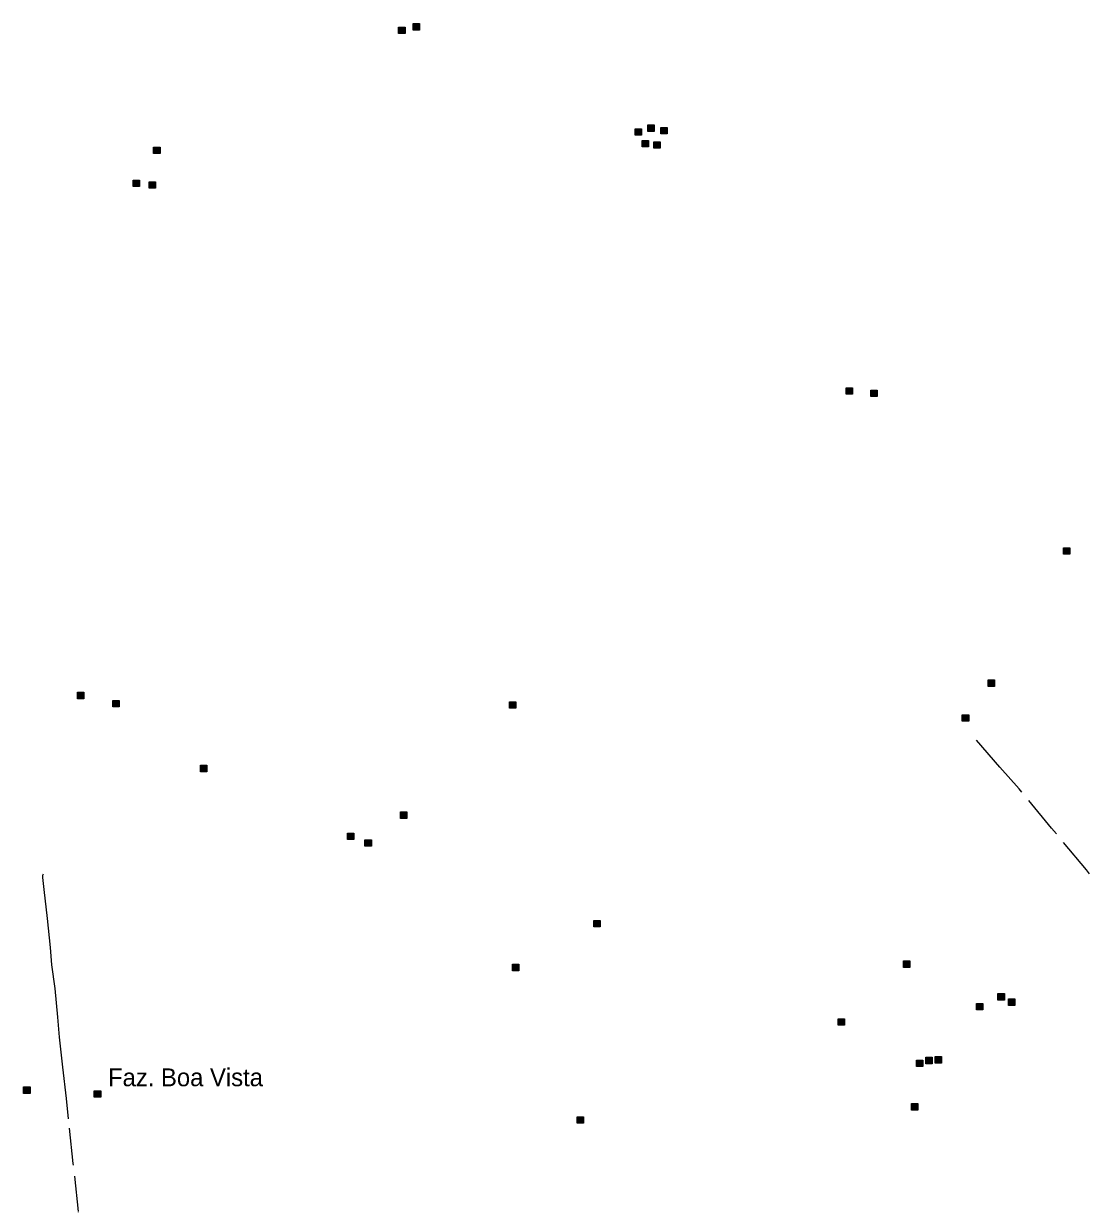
# Model space of a CAD drawing. Extents: x 393.5 to 446.9, y 8064.8 to 8120.4.
# Drawn here: x 437.25 to 446.82, y 8098.67 to 8109.28 of the extents above; entities that cross this region are included whole.
import ezdxf

# ---------------------------------------------------------------- set-up
doc = ezdxf.new("R2010")
doc.units = 0
doc.header["$LTSCALE"] = 0.064
doc.linetypes.add('DOT_DASHED', pattern=[7.7, 5, -1.2, 0.3, -1.2])
doc.layers.add('2', color=7, linetype='Continuous', lineweight=25)
doc.layers.add('22', color=7, linetype='DOT_DASHED', lineweight=13)
doc.layers.add('61', color=7, linetype='Continuous')

msp = doc.modelspace()

# ---------------------------------------------------------------- hatches: boundary and pattern name
at = {"layer": '2'}
for points in [[(440.6124, 8109.246), (440.6704, 8109.246), (440.6704, 8109.188), (440.6124, 8109.188)], [(440.7438, 8109.2772), (440.8018, 8109.2772), (440.8018, 8109.2192), (440.7438, 8109.2192)], [(442.7368, 8108.3317), (442.7948, 8108.3317), (442.7948, 8108.2737), (442.7368, 8108.2737)], [(442.8504, 8108.3665), (442.9084, 8108.3665), (442.9084, 8108.3085), (442.8504, 8108.3085)], [(442.9672, 8108.3451), (443.0252, 8108.3451), (443.0252, 8108.2871), (442.9672, 8108.2871)], [(438.4126, 8108.1683), (438.4706, 8108.1683), (438.4706, 8108.1103), (438.4126, 8108.1103)], [(442.7988, 8108.2276), (442.8568, 8108.2276), (442.8568, 8108.1696), (442.7988, 8108.1696)], [(442.9037, 8108.2149), (442.9617, 8108.2149), (442.9617, 8108.1569), (442.9037, 8108.1569)], [(438.2294, 8107.8717), (438.2874, 8107.8717), (438.2874, 8107.8137), (438.2294, 8107.8137)], [(438.3729, 8107.8561), (438.4309, 8107.8561), (438.4309, 8107.7981), (438.3729, 8107.7981)], [(444.6322, 8106.0064), (444.6902, 8106.0064), (444.6902, 8105.9484), (444.6322, 8105.9484)], [(444.853, 8105.9847), (444.911, 8105.9847), (444.911, 8105.9267), (444.853, 8105.9267)], [(446.5829, 8104.5696), (446.6409, 8104.5696), (446.6409, 8104.5116), (446.5829, 8104.5116)], [(445.9063, 8103.3817), (445.9643, 8103.3817), (445.9643, 8103.3237), (445.9063, 8103.3237)], [(437.7293, 8103.2704), (437.7873, 8103.2704), (437.7873, 8103.2124), (437.7293, 8103.2124)], [(438.0468, 8103.1968), (438.1048, 8103.1968), (438.1048, 8103.1388), (438.0468, 8103.1388)], [(441.6083, 8103.1857), (441.6663, 8103.1857), (441.6663, 8103.1277), (441.6083, 8103.1277)], [(445.6751, 8103.068), (445.7331, 8103.068), (445.7331, 8103.01), (445.6751, 8103.01)], [(438.8329, 8102.6152), (438.8909, 8102.6152), (438.8909, 8102.5572), (438.8329, 8102.5572)], [(440.6298, 8102.1951), (440.6878, 8102.1951), (440.6878, 8102.1371), (440.6298, 8102.1371)], [(440.1537, 8102.0062), (440.2117, 8102.0062), (440.2117, 8101.9482), (440.1537, 8101.9482)], [(440.3106, 8101.9461), (440.3686, 8101.9461), (440.3686, 8101.8881), (440.3106, 8101.8881)], [(442.3662, 8101.2209), (442.4242, 8101.2209), (442.4242, 8101.1629), (442.3662, 8101.1629)], [(445.1455, 8100.8572), (445.2035, 8100.8572), (445.2035, 8100.7992), (445.1455, 8100.7992)], [(441.6344, 8100.8274), (441.6924, 8100.8274), (441.6924, 8100.7694), (441.6344, 8100.7694)], [(445.9949, 8100.5642), (446.0529, 8100.5642), (446.0529, 8100.5062), (445.9949, 8100.5062)], [(445.8022, 8100.4751), (445.8602, 8100.4751), (445.8602, 8100.4171), (445.8022, 8100.4171)], [(446.0899, 8100.5153), (446.1479, 8100.5153), (446.1479, 8100.4573), (446.0899, 8100.4573)], [(444.5598, 8100.3371), (444.6178, 8100.3371), (444.6178, 8100.2791), (444.5598, 8100.2791)], [(445.4303, 8099.9975), (445.4883, 8099.9975), (445.4883, 8099.9395), (445.4303, 8099.9395)], [(445.2639, 8099.9658), (445.3219, 8099.9658), (445.3219, 8099.9078), (445.2639, 8099.9078)], [(445.3464, 8099.9923), (445.4044, 8099.9923), (445.4044, 8099.9343), (445.3464, 8099.9343)], [(437.2454, 8099.7252), (437.3034, 8099.7252), (437.3034, 8099.6672), (437.2454, 8099.6672)], [(437.8797, 8099.69), (437.9377, 8099.69), (437.9377, 8099.632), (437.8797, 8099.632)], [(445.2187, 8099.5756), (445.2767, 8099.5756), (445.2767, 8099.5176), (445.2187, 8099.5176)], [(442.2164, 8099.4574), (442.2744, 8099.4574), (442.2744, 8099.3994), (442.2164, 8099.3994)]]:
    msp.add_hatch(color=256, dxfattribs=at).paths.add_polyline_path(points)

# ---------------------------------------------------------------- linework, layer by layer
for points in [[(440.6124, 8109.246), (440.6704, 8109.246), (440.6704, 8109.188), (440.6124, 8109.188)], [(440.7438, 8109.2772), (440.8018, 8109.2772), (440.8018, 8109.2192), (440.7438, 8109.2192)], [(442.7368, 8108.3317), (442.7948, 8108.3317), (442.7948, 8108.2737), (442.7368, 8108.2737)], [(442.8504, 8108.3665), (442.9084, 8108.3665), (442.9084, 8108.3085), (442.8504, 8108.3085)], [(442.9672, 8108.3451), (443.0252, 8108.3451), (443.0252, 8108.2871), (442.9672, 8108.2871)], [(438.4126, 8108.1683), (438.4706, 8108.1683), (438.4706, 8108.1103), (438.4126, 8108.1103)], [(442.7988, 8108.2276), (442.8568, 8108.2276), (442.8568, 8108.1696), (442.7988, 8108.1696)], [(442.9037, 8108.2149), (442.9617, 8108.2149), (442.9617, 8108.1569), (442.9037, 8108.1569)], [(438.2294, 8107.8717), (438.2874, 8107.8717), (438.2874, 8107.8137), (438.2294, 8107.8137)], [(438.3729, 8107.8561), (438.4309, 8107.8561), (438.4309, 8107.7981), (438.3729, 8107.7981)], [(444.6322, 8106.0064), (444.6902, 8106.0064), (444.6902, 8105.9484), (444.6322, 8105.9484)], [(444.853, 8105.9847), (444.911, 8105.9847), (444.911, 8105.9267), (444.853, 8105.9267)], [(446.5829, 8104.5696), (446.6409, 8104.5696), (446.6409, 8104.5116), (446.5829, 8104.5116)], [(445.9063, 8103.3817), (445.9643, 8103.3817), (445.9643, 8103.3237), (445.9063, 8103.3237)], [(437.7293, 8103.2704), (437.7873, 8103.2704), (437.7873, 8103.2124), (437.7293, 8103.2124)], [(438.0468, 8103.1968), (438.1048, 8103.1968), (438.1048, 8103.1388), (438.0468, 8103.1388)], [(441.6083, 8103.1857), (441.6663, 8103.1857), (441.6663, 8103.1277), (441.6083, 8103.1277)], [(445.6751, 8103.068), (445.7331, 8103.068), (445.7331, 8103.01), (445.6751, 8103.01)], [(438.8329, 8102.6152), (438.8909, 8102.6152), (438.8909, 8102.5572), (438.8329, 8102.5572)], [(440.6298, 8102.1951), (440.6878, 8102.1951), (440.6878, 8102.1371), (440.6298, 8102.1371)], [(440.1537, 8102.0062), (440.2117, 8102.0062), (440.2117, 8101.9482), (440.1537, 8101.9482)], [(440.3106, 8101.9461), (440.3686, 8101.9461), (440.3686, 8101.8881), (440.3106, 8101.8881)], [(442.3662, 8101.2209), (442.4242, 8101.2209), (442.4242, 8101.1629), (442.3662, 8101.1629)], [(445.1455, 8100.8572), (445.2035, 8100.8572), (445.2035, 8100.7992), (445.1455, 8100.7992)], [(441.6344, 8100.8274), (441.6924, 8100.8274), (441.6924, 8100.7694), (441.6344, 8100.7694)], [(445.9949, 8100.5642), (446.0529, 8100.5642), (446.0529, 8100.5062), (445.9949, 8100.5062)], [(445.8022, 8100.4751), (445.8602, 8100.4751), (445.8602, 8100.4171), (445.8022, 8100.4171)], [(446.0899, 8100.5153), (446.1479, 8100.5153), (446.1479, 8100.4573), (446.0899, 8100.4573)], [(444.5598, 8100.3371), (444.6178, 8100.3371), (444.6178, 8100.2791), (444.5598, 8100.2791)], [(445.4303, 8099.9975), (445.4883, 8099.9975), (445.4883, 8099.9395), (445.4303, 8099.9395)], [(445.2639, 8099.9658), (445.3219, 8099.9658), (445.3219, 8099.9078), (445.2639, 8099.9078)], [(445.3464, 8099.9923), (445.4044, 8099.9923), (445.4044, 8099.9343), (445.3464, 8099.9343)], [(437.2454, 8099.7252), (437.3034, 8099.7252), (437.3034, 8099.6672), (437.2454, 8099.6672)], [(437.8797, 8099.69), (437.9377, 8099.69), (437.9377, 8099.632), (437.8797, 8099.632)], [(445.2187, 8099.5756), (445.2767, 8099.5756), (445.2767, 8099.5176), (445.2187, 8099.5176)], [(442.2164, 8099.4574), (442.2744, 8099.4574), (442.2744, 8099.3994), (442.2164, 8099.3994)]]:
    msp.add_lwpolyline(points, close=True, dxfattribs=at)
at = {"layer": '22'}
for points in [[(446.8161, 8101.6387), (446.7905, 8101.6762), (446.4765, 8102.0513), (446.1847, 8102.4024), (446.0109, 8102.5975), (445.7685, 8102.8782)], [(437.8357, 8097.6737), (437.8271, 8097.7543), (437.8185, 8097.8659), (437.7928, 8098.1062), (437.7741, 8098.2758), (437.738, 8098.6054), (437.6917, 8099.0375), (437.6488, 8099.4375), (437.6299, 8099.6201), (437.599, 8099.9016), (437.5689, 8100.1728), (437.5526, 8100.3514), (437.5277, 8100.6107), (437.4993, 8100.8236), (437.4873, 8100.9781), (437.459, 8101.2372), (437.4289, 8101.4999), (437.4194, 8101.608), (437.4194, 8101.6269), (437.4242, 8101.6408)]]:
    msp.add_lwpolyline(points, dxfattribs=at)

# ---------------------------------------------------------------- texts
at = {"layer": '61'}
msp.add_text('Faz. Boa Vista', height=0.16, dxfattribs=at).set_placement((438.0034, 8099.7315))

doc.saveas('drawing.dxf')
